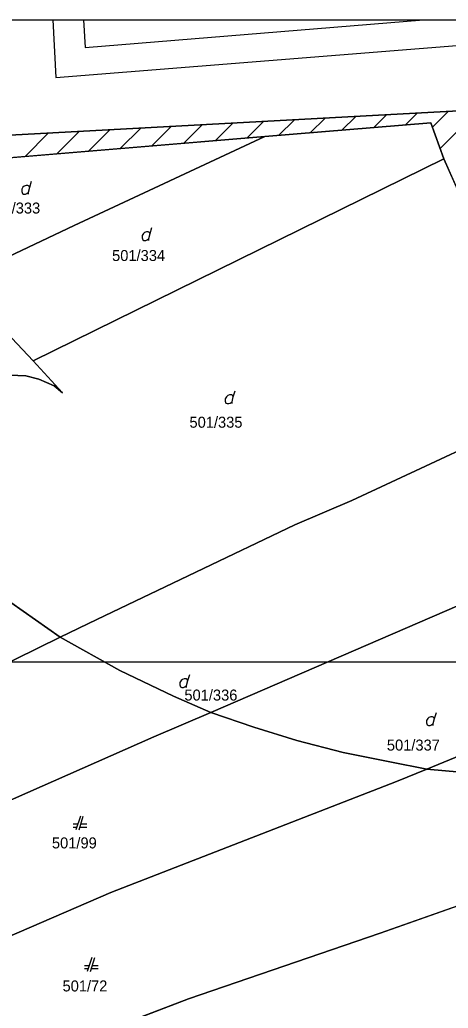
# Model space of a CAD drawing. Extents: x -264309 to -263505, y -1242443 to -1241763.
# Drawn here: x -264195.9 to -264133.4, y -1242101 to -1241957 of the extents above; entities that cross this region are included whole.
import ezdxf

# ---------------------------------------------------------------- set-up
doc = ezdxf.new("R2010")
doc.units = 0
for name, color, linetype in [('KN_2019_08_16_KLADPAR', 7, 'Continuous'), ('KN_2019_08_16_ZAPPAR', 7, 'Continuous'), ('RAM_NA_TLAC_10xA4_1-500', 7, 'Continuous'), ('SRAFY_PARCELY', 7, 'Continuous')]:
    doc.layers.add(name, color=color, linetype=linetype)

msp = doc.modelspace()

# ---------------------------------------------------------------- linework, layer by layer
at = {"layer": 'KN_2019_08_16_KLADPAR'}
for p, q in [((-264200.28, -1241956.96), (-264094.27, -1241956.96)), ((-264093.88, -1241968.2), (-264199.33, -1241973.87)), ((-264199.33, -1241973.87), (-264093.88, -1241968.2)), ((-264135.89, -1241972), (-264160.11, -1241973.99)), ((-264133.98, -1241977.23), (-264135.89, -1241972)), ((-264160.11, -1241973.99), (-264200.42, -1241977.31)), ((-264118.01, -1242013.33), (-264133.98, -1241977.23)), ((-264194.41, -1241981.37), (-264194.14, -1241980.47)), ((-264176.85, -1241988.13), (-264176.58, -1241987.23)), ((-264164.72, -1242011.92), (-264164.45, -1242011.02)), ((-264171.34, -1242053.28), (-264171.07, -1242052.38)), ((-264135.36, -1242058.82), (-264135.09, -1242057.92)), ((-264187.42, -1242074.23), (-264188.1, -1242074.23)), ((-264187, -1242073.03), (-264187.7, -1242075.03)), ((-264187.2, -1242075.03), (-264186.6, -1242073.03)), ((-264186.1, -1242074.23), (-264186.96, -1242074.23)), ((-264188.1, -1242074.63), (-264187.56, -1242074.63)), ((-264187.08, -1242074.63), (-264186.1, -1242074.63)), ((-264143.3, -1242090.1), (-264118.83, -1242081.48)), ((-264171.23, -1242099.67), (-264143.3, -1242090.1)), ((-264185.34, -1242093.66), (-264186.04, -1242095.66)), ((-264185.54, -1242095.66), (-264184.94, -1242093.66)), ((-264185.76, -1242094.86), (-264186.44, -1242094.86)), ((-264186.44, -1242095.26), (-264185.9, -1242095.26)), ((-264185.42, -1242095.26), (-264184.44, -1242095.26)), ((-264184.44, -1242094.86), (-264185.3, -1242094.86)), ((-264195.32, -1242108.83), (-264171.23, -1242099.67))]:
    msp.add_line(p, q, dxfattribs=at)
for points in [[(-264160.11, -1241973.99), (-264135.89, -1241972), (-264133.98, -1241977.23), (-264193.93, -1242006.68), (-264197.79, -1242002.53), (-264203.35, -1241994.24), (-264187.95, -1241986.93)], [(-264200.42, -1241977.31), (-264160.11, -1241973.99), (-264187.95, -1241986.93), (-264203.35, -1241994.24), (-264205.96, -1241990.34), (-264206.76, -1241988.71), (-264210.07, -1241981.92), (-264204.15, -1241979.03)], [(-264184.63, -1242044.36), (-264189.98, -1242046.97), (-264197.18, -1242041.92), (-264203.38, -1242036.91), (-264207.78, -1242033.03), (-264215.63, -1242024.82), (-264219.93, -1242019.72), (-264203.29, -1242011.27), (-264198.58, -1242008.96), (-264197.33, -1242008.76), (-264194.98, -1242008.87), (-264193.09, -1242009.32), (-264190.87, -1242010.33), (-264189.65, -1242011.32), (-264193.93, -1242006.68), (-264133.98, -1241977.23), (-264118.01, -1242013.33), (-264147.41, -1242027.03), (-264155.75, -1242030.57)], [(-264189.98, -1242046.97), (-264184.63, -1242044.36), (-264155.75, -1242030.57), (-264147.41, -1242027.03), (-264118.01, -1242013.33), (-264109.13, -1242032.5), (-264168.01, -1242057.92), (-264173.43, -1242055.54), (-264181.27, -1242051.82)], [(-264215.64, -1242060.08), (-264232.73, -1242069.28), (-264271.31, -1242088.83), (-264283.31, -1242095.71), (-264305.18, -1242063.04), (-264287.97, -1242054.01), (-264269.44, -1242044.29), (-264233.57, -1242026.64), (-264219.93, -1242019.72), (-264215.63, -1242024.82), (-264207.78, -1242033.03), (-264203.38, -1242036.91), (-264197.18, -1242041.92), (-264189.98, -1242046.97), (-264203.07, -1242053.35)], [(-264109.13, -1242032.5), (-264100, -1242051.16), (-264136.47, -1242066.18), (-264141.87, -1242065.13), (-264148.68, -1242063.74), (-264155.45, -1242062), (-264161.74, -1242060.05), (-264168.01, -1242057.92)], [(-264232.73, -1242069.28), (-264215.64, -1242060.08), (-264203.07, -1242053.35), (-264189.98, -1242046.97), (-264181.27, -1242051.82), (-264173.43, -1242055.54), (-264168.01, -1242057.92), (-264176.29, -1242061.5), (-264207.3, -1242075.14), (-264227.48, -1242084.41), (-264254.05, -1242097.99), (-264274.79, -1242109.56), (-264278.66, -1242103.27), (-264283.31, -1242095.71), (-264271.31, -1242088.83)], [(-264126.66, -1242067.07), (-264136.47, -1242066.18), (-264100, -1242051.16), (-264093.07, -1242066.63), (-264113.43, -1242067.44)], [(-264168.01, -1242057.92), (-264161.74, -1242060.05), (-264155.45, -1242062), (-264148.68, -1242063.74), (-264141.87, -1242065.13), (-264136.47, -1242066.18), (-264140.89, -1242068), (-264182.59, -1242084.17), (-264197.75, -1242090.71), (-264231.21, -1242105.15), (-264240.95, -1242110.43), (-264265.78, -1242123.95), (-264268.86, -1242119.03), (-264274.79, -1242109.56), (-264254.05, -1242097.99), (-264227.48, -1242084.41), (-264207.3, -1242075.14), (-264176.29, -1242061.5)], [(-264136.47, -1242066.18), (-264126.66, -1242067.07), (-264113.43, -1242067.44), (-264093.07, -1242066.63), (-264091, -1242071.24), (-264106.54, -1242077.18), (-264118.83, -1242081.48), (-264143.3, -1242090.1), (-264171.23, -1242099.67), (-264195.32, -1242108.83), (-264231.66, -1242125.67), (-264256.42, -1242138.67), (-264258.61, -1242135.22), (-264265.78, -1242123.95), (-264240.95, -1242110.43), (-264231.21, -1242105.15), (-264197.75, -1242090.71), (-264182.59, -1242084.17), (-264140.89, -1242068)]]:
    msp.add_lwpolyline(points, close=True, dxfattribs=at)
for points in [[(-264194.59, -1241982.36), (-264194.59, -1241982.09), (-264194.41, -1241981.37), (-264194.5, -1241981.19), (-264194.68, -1241981.1), (-264194.95, -1241981.1), (-264195.22, -1241981.19), (-264195.4, -1241981.37), (-264195.58, -1241981.64), (-264195.58, -1241982), (-264195.49, -1241982.27), (-264195.31, -1241982.36), (-264195.04, -1241982.36), (-264194.86, -1241982.27), (-264194.59, -1241982.09)], [(-264177.03, -1241989.12), (-264177.03, -1241988.85), (-264176.85, -1241988.13), (-264176.94, -1241987.95), (-264177.12, -1241987.86), (-264177.39, -1241987.86), (-264177.66, -1241987.95), (-264177.84, -1241988.13), (-264178.02, -1241988.4), (-264178.02, -1241988.76), (-264177.93, -1241989.03), (-264177.75, -1241989.12), (-264177.48, -1241989.12), (-264177.3, -1241989.03), (-264177.03, -1241988.85)], [(-264197.79, -1242002.53), (-264193.93, -1242006.68), (-264189.65, -1242011.32), (-264190.87, -1242010.33), (-264193.09, -1242009.32), (-264194.98, -1242008.87), (-264197.33, -1242008.76)], [(-264164.9, -1242012.91), (-264164.9, -1242012.64), (-264164.72, -1242011.92), (-264164.81, -1242011.74), (-264164.99, -1242011.65), (-264165.26, -1242011.65), (-264165.53, -1242011.74), (-264165.71, -1242011.92), (-264165.89, -1242012.19), (-264165.89, -1242012.55), (-264165.8, -1242012.82), (-264165.62, -1242012.91), (-264165.35, -1242012.91), (-264165.17, -1242012.82), (-264164.9, -1242012.64)], [(-264171.52, -1242054.27), (-264171.52, -1242054), (-264171.34, -1242053.28), (-264171.43, -1242053.1), (-264171.61, -1242053.01), (-264171.88, -1242053.01), (-264172.15, -1242053.1), (-264172.33, -1242053.28), (-264172.51, -1242053.55), (-264172.51, -1242053.91), (-264172.42, -1242054.18), (-264172.24, -1242054.27), (-264171.97, -1242054.27), (-264171.79, -1242054.18), (-264171.52, -1242054)], [(-264135.54, -1242059.81), (-264135.54, -1242059.54), (-264135.36, -1242058.82), (-264135.45, -1242058.64), (-264135.63, -1242058.55), (-264135.9, -1242058.55), (-264136.17, -1242058.64), (-264136.35, -1242058.82), (-264136.53, -1242059.09), (-264136.53, -1242059.45), (-264136.44, -1242059.72), (-264136.26, -1242059.81), (-264135.99, -1242059.81), (-264135.81, -1242059.72), (-264135.54, -1242059.54)]]:
    msp.add_lwpolyline(points, dxfattribs=at)
at = {"layer": 'KN_2019_08_16_ZAPPAR'}
for p, q in [((-264191.06, -1241956.96), (-264190.63, -1241965.35)), ((-264186.56, -1241956.96), (-264186.35, -1241961))]:
    msp.add_line(p, q, dxfattribs=at)
for points in [[(-264190.63, -1241965.35), (-264096.18, -1241957.82), (-264096.28, -1241956.96)], [(-264186.35, -1241961), (-264136.95, -1241956.96)]]:
    msp.add_lwpolyline(points, dxfattribs=at)
at = {"layer": 'RAM_NA_TLAC_10xA4_1-500'}
msp.add_lwpolyline([(-264210.83, -1242050.54), (-264105.83, -1242050.54), (-264000.83, -1242050.54), (-263895.83, -1242050.54), (-263790.83, -1242050.54), (-263685.83, -1242050.54), (-263685.83, -1242199.04), (-263685.83, -1242347.54), (-263790.83, -1242347.54), (-263895.83, -1242347.54), (-264000.83, -1242347.54), (-264105.83, -1242347.54), (-264210.83, -1242347.54), (-264210.83, -1242199.04)], close=True, dxfattribs=at)
at = {"layer": 'SRAFY_PARCELY'}
for p, q in [((-264139.62, -1241972.31), (-264137.88, -1241970.57)), ((-264135.67, -1241972.6), (-264133.39, -1241970.32)), ((-264134.54, -1241975.71), (-264128.91, -1241970.08)), ((-264167.35, -1241974.59), (-264164.78, -1241972.01)), ((-264162.73, -1241974.21), (-264160.3, -1241971.77)), ((-264158.11, -1241973.83), (-264155.81, -1241971.53)), ((-264153.48, -1241973.45), (-264151.33, -1241971.29)), ((-264148.86, -1241973.07), (-264146.84, -1241971.05)), ((-264144.24, -1241972.69), (-264142.36, -1241970.81)), ((-264195.09, -1241976.87), (-264191.68, -1241973.46)), ((-264190.47, -1241976.49), (-264187.2, -1241973.22)), ((-264185.85, -1241976.11), (-264182.71, -1241972.98)), ((-264181.22, -1241975.73), (-264178.23, -1241972.74)), ((-264176.6, -1241975.35), (-264173.75, -1241972.49)), ((-264171.98, -1241974.97), (-264169.26, -1241972.25))]:
    msp.add_line(p, q, dxfattribs=at)

# ---------------------------------------------------------------- texts
at = {"layer": 'KN_2019_08_16_KLADPAR'}
for s, p in [('501/333', (-264200.62, -1241985.2)), ('501/334', (-264182.4, -1241992.12)), ('501/335', (-264171.11, -1242016.42)), ('501/336', (-264171.85, -1242056.19)), ('501/337', (-264142.31, -1242063.48)), ('501/99', (-264191.18, -1242077.74)), ('501/72', (-264189.63, -1242098.59))]:
    msp.add_text(s, height=1.6, dxfattribs=at).set_placement(p)

doc.saveas('drawing.dxf')
